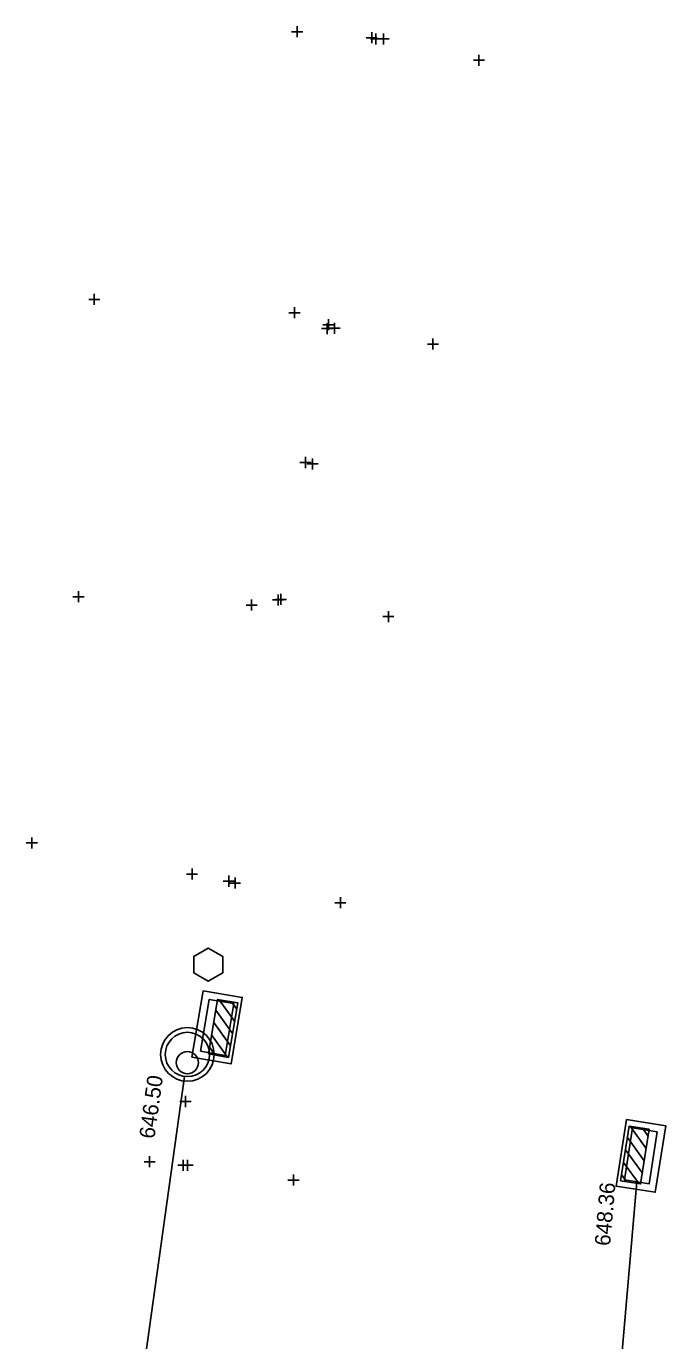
# Model space of a CAD drawing. Extents: x 2188719 to 2189819, y 654569 to 659504.
# Drawn here: x 2189557.4 to 2189615.1, y 656405.5 to 656524.1 of the extents above; entities that cross this region are included whole.
import ezdxf

# ---------------------------------------------------------------- set-up
doc = ezdxf.new("R2010")
doc.units = 0
for name, color, linetype in [('DR_X_Cells', 7, 'Continuous'), ('DR_X_Storm_Sewer', 7, 'Continuous'), ('GK_Drainage_Nodes', 7, 'Continuous'), ('RD_X_Cells', 7, 'Continuous'), ('SC_Scratch1', 7, 'Continuous'), ('SV_X_Shot_Marker', 7, 'Continuous')]:
    doc.layers.add(name, color=color, linetype=linetype)

msp = doc.modelspace()

# ---------------------------------------------------------------- linework, layer by layer
at = {"layer": 'DR_X_Cells'}
for p, q in [((2189576.19, 656434.34), (2189574.8, 656436.28)), ((2189576.37, 656435.46), (2189575.92, 656436.1)), ((2189576, 656433.23), (2189574.49, 656435.34)), ((2189575.81, 656432.11), (2189574.31, 656434.22)), ((2189575.56, 656431.09), (2189574.12, 656433.11)), ((2189574.44, 656431.27), (2189573.93, 656431.99)), ((2189611.89, 656424.87), (2189613.35, 656422.86)), ((2189613, 656424.69), (2189613.53, 656423.97)), ((2189611.47, 656422.72), (2189613, 656420.63)), ((2189611.65, 656423.83), (2189613.17, 656421.74)), ((2189611.3, 656421.6), (2189612.7, 656419.67)), ((2189611.12, 656420.49), (2189611.58, 656419.85))]:
    msp.add_line(p, q, dxfattribs=at)
for points in [[(2189572.34, 656431.08), (2189573.35, 656437.08), (2189576.88, 656436.48), (2189575.87, 656430.48)], [(2189573.11, 656431.63), (2189573.9, 656436.31), (2189576.12, 656435.94), (2189575.33, 656431.25)], [(2189573.83, 656431.38), (2189574.66, 656436.31), (2189576.47, 656436), (2189575.63, 656431.07)], [(2189615.11, 656424.91), (2189614.16, 656418.9), (2189610.62, 656419.45), (2189611.57, 656425.46)], [(2189613.62, 656424.59), (2189612.84, 656419.65), (2189611.03, 656419.94), (2189611.81, 656424.88)], [(2189614.34, 656424.35), (2189613.61, 656419.66), (2189611.38, 656420.01), (2189612.12, 656424.7)]]:
    msp.add_lwpolyline(points, close=True, dxfattribs=at)
for centre, radius in [((2189571.93, 656431.34), 2.42), ((2189571.93, 656431.34), 2), ((2189571.93, 656430.6), 1)]:
    msp.add_circle(centre, radius, dxfattribs=at)
at = {"layer": 'DR_X_Storm_Sewer'}
for p, q in [((2189571.66, 656429.36), (2189561.96, 656359.37)), ((2189612.49, 656419.83), (2189606.4, 656349.47))]:
    msp.add_line(p, q, dxfattribs=at)
at = {"layer": 'GK_Drainage_Nodes'}
for p, q in [((2189575.01, 656436.12), (2189575.01, 656436.12)), ((2189571.93, 656433.34), (2189571.93, 656433.34)), ((2189572.85, 656434.08), (2189572.85, 656434.08)), ((2189573.5, 656433.97), (2189573.5, 656433.97)), ((2189574.24, 656433.84), (2189574.24, 656433.84)), ((2189574.24, 656433.84), (2189574.24, 656433.84)), ((2189574.61, 656433.78), (2189574.61, 656433.78)), ((2189575.72, 656433.59), (2189575.72, 656433.59)), ((2189576.38, 656433.48), (2189576.38, 656433.48)), ((2189571.93, 656431.34), (2189571.93, 656431.34)), ((2189571.93, 656431.34), (2189571.93, 656431.34)), ((2189574.22, 656431.44), (2189574.22, 656431.44)), ((2189571.93, 656430.6), (2189571.93, 656430.6)), ((2189571.93, 656429.35), (2189571.93, 656429.35)), ((2189613.23, 656424.53), (2189613.23, 656424.53)), ((2189611.09, 656422.46), (2189611.09, 656422.46)), ((2189611.75, 656422.36), (2189611.75, 656422.36)), ((2189612.86, 656422.18), (2189612.86, 656422.18)), ((2189613.23, 656422.12), (2189613.23, 656422.12)), ((2189613.23, 656422.12), (2189613.23, 656422.12)), ((2189613.97, 656422.01), (2189613.97, 656422.01)), ((2189614.63, 656421.9), (2189614.63, 656421.9)), ((2189612.49, 656419.83), (2189612.49, 656419.83))]:
    msp.add_line(p, q, dxfattribs=at)
msp.add_circle((2189571.93, 656431.34), 2, dxfattribs=at)
at = {"layer": 'RD_X_Cells'}
msp.add_lwpolyline([(2189572.52, 656438.69), (2189573.82, 656437.94), (2189575.12, 656438.69), (2189575.12, 656440.19), (2189573.82, 656440.94), (2189572.52, 656440.19), (2189572.52, 656438.69)], dxfattribs=at)
at = {"layer": 'SV_X_Shot_Marker'}
for p, q in [((2189581.34, 656523.64), (2189582.34, 656523.64)), ((2189581.84, 656524.14), (2189581.84, 656523.14)), ((2189581.84, 656523.64), (2189581.84, 656523.64)), ((2189588.57, 656523.6), (2189588.57, 656522.6)), ((2189588.95, 656523.5), (2189588.95, 656522.5)), ((2189589.64, 656523.49), (2189589.64, 656522.49)), ((2189588.07, 656523.1), (2189589.07, 656523.1)), ((2189588.45, 656523), (2189589.45, 656523)), ((2189588.57, 656523.1), (2189588.57, 656523.1)), ((2189588.95, 656523), (2189588.95, 656523)), ((2189589.14, 656522.99), (2189590.14, 656522.99)), ((2189589.64, 656522.99), (2189589.64, 656522.99)), ((2189598.25, 656521.57), (2189598.25, 656520.57)), ((2189597.75, 656521.07), (2189598.75, 656521.07)), ((2189598.25, 656521.07), (2189598.25, 656521.07)), ((2189563.52, 656499.99), (2189563.52, 656498.99)), ((2189563.02, 656499.49), (2189564.02, 656499.49)), ((2189563.52, 656499.49), (2189563.52, 656499.49)), ((2189581.6, 656498.78), (2189581.6, 656497.78)), ((2189581.1, 656498.28), (2189582.1, 656498.28)), ((2189581.6, 656498.28), (2189581.6, 656498.28)), ((2189584.66, 656497.7), (2189584.66, 656496.7)), ((2189584.05, 656496.85), (2189585.05, 656496.85)), ((2189584.16, 656497.2), (2189585.16, 656497.2)), ((2189584.55, 656497.35), (2189584.55, 656496.35)), ((2189584.55, 656496.85), (2189584.55, 656496.85)), ((2189584.66, 656497.2), (2189584.66, 656497.2)), ((2189584.71, 656496.88), (2189585.71, 656496.88)), ((2189585.21, 656497.38), (2189585.21, 656496.38)), ((2189585.21, 656496.88), (2189585.21, 656496.88)), ((2189593.59, 656495.45), (2189594.59, 656495.45)), ((2189594.09, 656495.95), (2189594.09, 656494.95)), ((2189594.09, 656495.45), (2189594.09, 656495.45)), ((2189582.08, 656484.78), (2189583.08, 656484.78)), ((2189582.1, 656484.76), (2189583.1, 656484.76)), ((2189582.58, 656485.28), (2189582.58, 656484.28)), ((2189582.58, 656484.78), (2189582.58, 656484.78)), ((2189582.6, 656485.26), (2189582.6, 656484.26)), ((2189582.6, 656484.76), (2189582.6, 656484.76)), ((2189582.73, 656484.63), (2189583.73, 656484.63)), ((2189583.23, 656485.13), (2189583.23, 656484.13)), ((2189583.23, 656484.63), (2189583.23, 656484.63)), ((2189561.6, 656472.65), (2189562.6, 656472.65)), ((2189562.1, 656473.15), (2189562.1, 656472.15)), ((2189562.1, 656472.65), (2189562.1, 656472.65)), ((2189580.11, 656472.86), (2189580.11, 656471.86)), ((2189580.37, 656472.91), (2189580.37, 656471.91)), ((2189577.23, 656471.9), (2189578.23, 656471.9)), ((2189577.73, 656472.4), (2189577.73, 656471.4)), ((2189577.73, 656471.9), (2189577.73, 656471.9)), ((2189579.61, 656472.36), (2189580.61, 656472.36)), ((2189579.87, 656472.41), (2189580.87, 656472.41)), ((2189580.11, 656472.36), (2189580.11, 656472.36)), ((2189580.37, 656472.41), (2189580.37, 656472.41)), ((2189590.07, 656471.36), (2189590.07, 656470.36)), ((2189589.57, 656470.86), (2189590.57, 656470.86)), ((2189590.07, 656470.86), (2189590.07, 656470.86)), ((2189557.39, 656450.43), (2189558.39, 656450.43)), ((2189557.89, 656450.93), (2189557.89, 656449.93)), ((2189557.89, 656450.43), (2189557.89, 656450.43)), ((2189571.85, 656447.62), (2189572.85, 656447.62)), ((2189572.35, 656448.12), (2189572.35, 656447.12)), ((2189572.35, 656447.62), (2189572.35, 656447.62)), ((2189575.17, 656446.98), (2189576.17, 656446.98)), ((2189575.67, 656447.48), (2189575.67, 656446.48)), ((2189575.67, 656446.98), (2189575.67, 656446.98)), ((2189575.73, 656446.81), (2189576.73, 656446.81)), ((2189576.23, 656447.31), (2189576.23, 656446.31)), ((2189576.23, 656446.81), (2189576.23, 656446.81)), ((2189585.74, 656445.53), (2189585.74, 656444.53)), ((2189585.24, 656445.03), (2189586.24, 656445.03)), ((2189585.74, 656445.03), (2189585.74, 656445.03)), ((2189571.76, 656427.59), (2189571.76, 656426.59)), ((2189571.26, 656427.09), (2189572.26, 656427.09)), ((2189571.76, 656427.09), (2189571.76, 656427.09)), ((2189568.02, 656421.66), (2189569.02, 656421.66)), ((2189568.52, 656422.16), (2189568.52, 656421.16)), ((2189568.52, 656421.66), (2189568.52, 656421.66)), ((2189571.56, 656421.84), (2189571.56, 656420.84)), ((2189571.94, 656421.84), (2189571.94, 656420.84)), ((2189571.06, 656421.34), (2189572.06, 656421.34)), ((2189571.44, 656421.34), (2189572.44, 656421.34)), ((2189571.56, 656421.34), (2189571.56, 656421.34)), ((2189571.94, 656421.34), (2189571.94, 656421.34)), ((2189581.51, 656420.5), (2189581.51, 656419.5)), ((2189581.01, 656420), (2189582.01, 656420)), ((2189581.51, 656420), (2189581.51, 656420))]:
    msp.add_line(p, q, dxfattribs=at)

# ---------------------------------------------------------------- texts
at = {"layer": 'SC_Scratch1'}
for s, rotation, p in [('646.50', 82.1157, (2189568.95, 656423.68)), ('648.36', 85.0538, (2189610.08, 656414.02))]:
    msp.add_text(s, height=1.4, rotation=rotation, dxfattribs=at).set_placement(p)

doc.saveas('drawing.dxf')
